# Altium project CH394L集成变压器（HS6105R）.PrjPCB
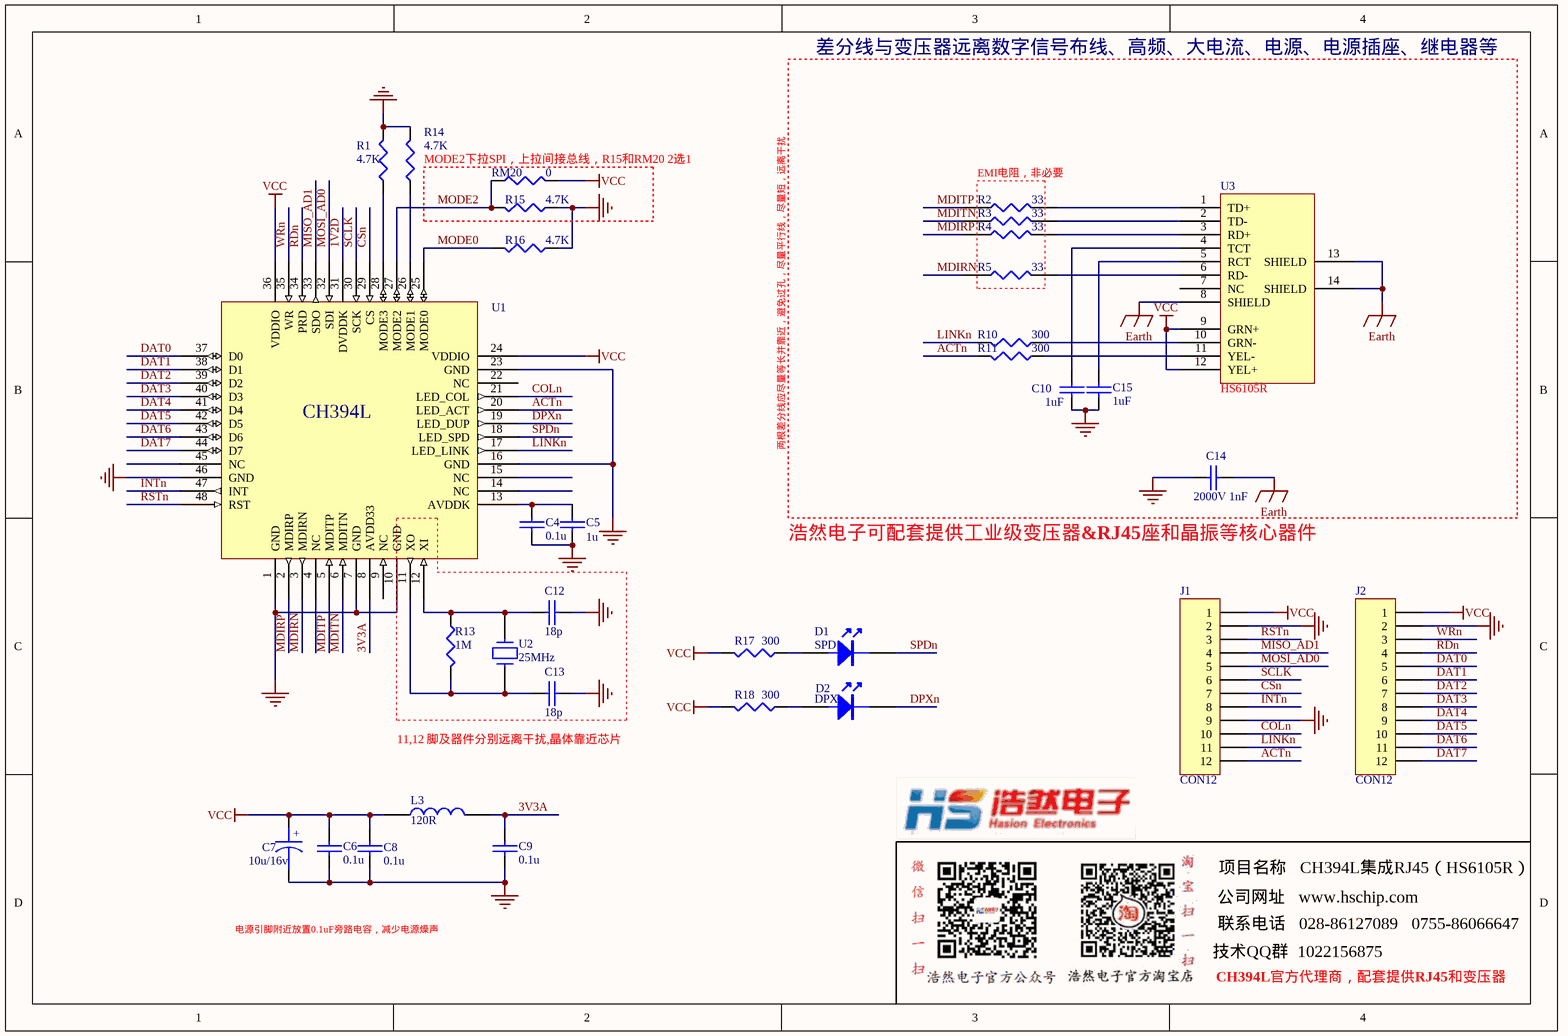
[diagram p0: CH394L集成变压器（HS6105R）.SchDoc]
1 sheet, 33 parts. Net scope: global (net labels, ports and power ports of the same name join across sheets).

## Sheet CH394L集成变压器（HS6105R）.SchDoc
size A4; SheetNumber: 0; SheetTotal: 0; PageSetup: Record=PageOptions?CenterHorizontal=True?CenterVertical=True?PrintScale=1.00?XCorrection=1.00?YCorrection=1.00?PrintKind=0?BorderSize=5000000?LeftOffset=0?BottomOffset=0?Orientation=2?PaperLength=1000?PaperWidth=1000?Scale=100?PaperSource=7?PrintQuality=-4?MediaType=1?DitherType=10?PaperKind=A4?PrintScaleMode=1

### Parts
C4  0.1u  [0603]
C5  1u  [0603]
C6  0.1u  [0603]
C7  10u/16v  [3216]
C8  0.1u  [0603]
C9  0.1u  [0603]
C10  1uF  [0603]
C12  18p  [0603]
C13  18p  [0603]
C14  2000V 1nF  [3216]
C15  1uF  [0603]
D1  SPD
D2  DPX
J1  CON12  [SIP12]
J2  CON12  [SIP12]
L3  120R  [0603]
R1  4.7K  [0603]
R2  33  [0603]
R3  33  [0603]
R4  33  [0603]
R5  33  [0603]
R10  300  [0603]
R11  300  [0603]
R13  1M  [0603]
R14  4.7K  [0603]
R15  4.7K  [0603]
R16  4.7K  [0603]
R17  300  [0603]
R18  300  [0603]
RM20  0  [0603]
U1  CH394L  [LQFP48-W5500/W5100S/W6100/C8T6]
U2  25MHz  [XTAL-49S]
U3  HS6105R  [RJ45-HS6105R]

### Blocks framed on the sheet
差分线与变压器远离数字信号布线、高频、大电流、电源、电源插座、继电器等: C10 C14 C15 R10 R11 U3
MODE2下拉SPI，上拉间接总线，R15和RM20 2选1: R15 RM20
EMI电阻，非必要: R2-R5

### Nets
Earth: C14.1 U3.8(SHIELD) U3.13(SHIELD) U3.14(SHIELD)
GND: C4.2 C5.2 C6.2 C7.2 C8.2 C9.2 C10.2 C12.2 C13.2 C14.2 C15.1 J1.2 J1.9 J2.2 R1.2 R14.2 R15.1 R16.1 U1.1(GND) U1.7(GND) U1.10(GND) U1.16(GND) U1.23(GND) U1.46(GND)
VCC: C6.1 C7.1 C8.1 J1.1 J2.1 L3.1 R17.2 R18.2 RM20.2 U1.24(VDDIO) U1.36(VDDIO) U3.9(GRN+) U3.12(YEL+)
1V2D: U1.31(DVDDK)
3V3A: C9.1 L3.2 U1.8(AVDD33)
ACTn: J1.12 R11.2 U1.20(LED_ACT)
COLn: J1.10 U1.21(LED_COL)
CSn: J1.7 U1.29(CS)
DAT0: J2.5 U1.37(D0)
DAT1: J2.6 U1.38(D1)
DAT2: J2.7 U1.39(D2)
DAT3: J2.8 U1.40(D3)
DAT4: J2.9 U1.41(D4)
DAT5: J2.10 U1.42(D5)
DAT6: J2.11 U1.43(D6)
DAT7: J2.12 U1.44(D7)
DPXn: D2.K U1.19(LED_DUP)
INTn: J1.8 U1.47(INT)
LINKn: J1.11 R10.2 U1.17(LED_LINK)
MDIRN: R5.1 U1.3(MDIRN)
MDIRP: R4.1 U1.2(MDIRP)
MDITN: R3.1 U1.6(MDITN)
MDITP: R2.1 U1.5(MDITP)
MISO_AD1: J1.4 U1.33(SDO)
MODE0: R16.2 U1.25(MODE0)
MODE2: R15.2 RM20.1 U1.27(MODE2)
MOSI_AD0: J1.5 U1.32(SDI)
RDn: J2.4 U1.34(PRD)
RSTn: J1.3 U1.48(RST)
SCLK: J1.6 U1.30(SCK)
SPDn: D1.K U1.18(LED_SPD)
WRn: J2.3 U1.35(WR)
NetC4_1: C4.1 C5.1 U1.13(AVDDK)
NetC10_1: C10.1 U3.4(TCT)
NetC12_1: C12.1 R13.1 U1.12(XI) U2.2
NetC13_1: C13.1 R13.2 U1.11(XO) U2.1
NetC15_2: C15.2 U3.5(RCT)
NetD1_A: D1.A R17.1
NetD2_A: D2.A R18.1
NetR1_1: R1.1 U1.28(MODE3)
NetR2_2: R2.2 U3.1(TD+)
NetR3_2: R3.2 U3.2(TD-)
NetR4_2: R4.2 U3.3(RD+)
NetR5_2: R5.2 U3.6(RD-)
NetR10_1: R10.1 U3.10(GRN-)
NetR11_1: R11.1 U3.11(YEL-)
NetR14_1: R14.1 U1.26(MODE1)

Not connected (* = marked no-connect by the designer): U1 4(NC) 9(NC) 14(NC) 15(NC) 22(NC) 45(NC); U3 7(NC)

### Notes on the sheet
- 两根差分线应尽量等长并靠近，避免过孔，尽量平行线，尽量短，远离干扰
- (near C13) 11,12 脚及器件分别远离干扰,晶体靠近芯片
- 公司网址   www.hschip.com
- 项目名称   CH394L集成RJ45（HS6105R）
- 电源引脚附近放置0.1uF旁路电容，减少电源燥声
- 技术QQ群  1022156875
- CH394L官方代理商，配套提供RJ45和变压器
- 联系电话   028-86127089   0755-86066647
- Labels drawn without touching a wire or pin: 浩然电子可配套提供工业级变压器&RJ45座和晶振等核心器件

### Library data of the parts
C4-C6 C8-C10 C12-C15 = CAP: Capacitor
C7 = CAPACITOR POL: Capacitor
D1 D2 = LED
J1 J2 = CON12: Connector
L3 = INDUCTOR
R1-R5 R10 R11 R13-R18 RM20 = RES1
U2 = CRYSTAL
